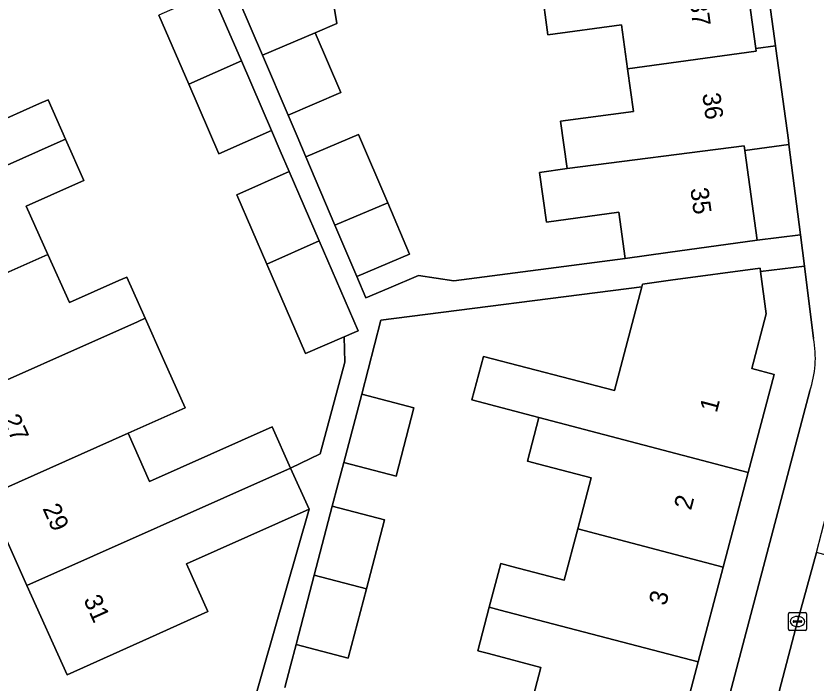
# Model space of a CAD drawing. Extents: x 163147 to 163550, y 380933 to 381639.
# Drawn here: x 163305.41 to 163349.73, y 381146.66 to 381183.65 of the extents above; entities that cross this region are included whole.
import ezdxf

# ---------------------------------------------------------------- set-up
doc = ezdxf.new("R2010")
doc.units = 0
for name, color, linetype in [('IMGEO_Erf', 7, 'Continuous'), ('IMGEO_Kolk', 7, 'Continuous'), ('IMGEO_Pand', 7, 'Continuous'), ('IMGEO_Pand_nummerreeks', 7, 'Continuous'), ('IMGEO_Rijbaan_lokaal_open', 7, 'Continuous'), ('IMGEO_Voetpad_open', 7, 'Continuous')]:
    doc.layers.add(name, color=color, linetype=linetype)

msp = doc.modelspace()

# ---------------------------------------------------------------- linework, layer by layer
at = {"layer": 'IMGEO_Erf'}
for points in [[(163346.127, 381191.825), (163345.039, 381191.675), (163345.711, 381186.784), (163346.388, 381181.854), (163347.476, 381182.004)], [(163348.228, 381176.531), (163345.784, 381176.195), (163346.465, 381171.235), (163348.863, 381171.54)]]:
    msp.add_lwpolyline(points, close=True, dxfattribs=at)
for points in [[(163322.634, 381186.622), (163323.179, 381183.235), (163321.987, 381182.727), (163323.4, 381179.41), (163320.478, 381178.166), (163320.979, 381176.991), (163321.463, 381175.854), (163324.384, 381177.098), (163326.001, 381173.304), (163327.21, 381170.465), (163324.289, 381169.221), (163324.79, 381168.045), (163326.066, 381168.588), (163327.711, 381169.289), (163329.659, 381168.981), (163339.151, 381170.231), (163338.8, 381172.786), (163334.788, 381172.235), (163334.409, 381174.99), (163335.937, 381175.2), (163335.579, 381177.82), (163339.611, 381178.372), (163339.288, 381180.725), (163338.953, 381183.168), (163334.875, 381182.608), (163334.513, 381185.247)], [(163303.971, 381177.58), (163306.712, 381178.8), (163307.181, 381179.008), (163308.15, 381176.83), (163309.167, 381174.546), (163308.711, 381174.343), (163305.97, 381173.124), (163307.17, 381170.451), (163308.368, 381167.78), (163311.109, 381168.999), (163311.548, 381169.194), (163312.564, 381166.91), (163313.58, 381164.626), (163314.77, 381161.953), (163311.613, 381160.548), (163312.812, 381157.875), (163319.597, 381160.894), (163320.621, 381158.613), (163322.266, 381159.409), (163323.626, 381164.485), (163323.596, 381165.887), (163321.443, 381164.955), (163319.299, 381169.906), (163317.634, 381173.75), (163320.543, 381175.044), (163320.051, 381176.181), (163319.562, 381177.31), (163316.653, 381176.016), (163314.984, 381179.869), (163313.326, 381183.697)], [(163349.596, 381165.787), (163349.084, 381169.804), (163346.653, 381169.495), (163346.974, 381167.164), (163346.173, 381164.127), (163347.401, 381163.803), (163345.971, 381158.376), (163344.588, 381153.128), (163343.205, 381147.878), (163341.822, 381142.63)], [(163333.739, 381144.749), (163334.49, 381147.578), (163331.588, 381148.339), (163330.992, 381148.495), (163331.626, 381150.913), (163332.26, 381153.331), (163332.871, 381153.171), (163335.773, 381152.411), (163336.524, 381155.242), (163337.275, 381158.071), (163334.373, 381158.831), (163333.745, 381158.996), (163334.38, 381161.414), (163330.669, 381162.387), (163331.31, 381164.803), (163338.557, 381162.903), (163340.084, 381168.658), (163325.613, 381166.816), (163324.563, 381162.709), (163327.456, 381161.951), (163326.46, 381158.158), (163323.567, 381158.917), (163323.246, 381157.696), (163322.932, 381156.501), (163325.825, 381155.742), (163324.821, 381151.924), (163323.831, 381148.154), (163323.815, 381148.093), (163320.923, 381148.853), (163320.612, 381147.671), (163320.294, 381146.461)], [(163334.439, 381106.274), (163349.385, 381162.891)], [(163304.985, 381145.89), (163307.687, 381144.941), (163309.044, 381145.786), (163318.448, 381145.215), (163321.644, 381156.332), (163314.859, 381153.313), (163316.043, 381150.675), (163312.795, 381149.218), (163308.233, 381147.171), (163306.015, 381152.115), (163303.793, 381157.068)]]:
    msp.add_lwpolyline(points, dxfattribs=at)
msp.add_arc((163343.933, 381164.744), 5.758, 341.2296, 10.4361, dxfattribs=at)
at = {"layer": 'IMGEO_Kolk'}
for p, q in [((163348.2, 381149.692), (163348.2, 381150.544)), ((163348.275, 381150.618), (163349.127, 381150.618)), ((163349.201, 381150.544), (163349.201, 381149.692)), ((163348.459, 381150.112), (163348.459, 381150.124)), ((163348.897, 381150.075), (163348.499, 381150.075)), ((163348.502, 381150.161), (163348.9, 381150.161)), ((163348.688, 381150.398), (163348.713, 381150.398)), ((163348.943, 381150.124), (163348.943, 381150.112)), ((163349.127, 381149.618), (163348.275, 381149.618)), ((163348.711, 381149.838), (163348.686, 381149.838))]:
    msp.add_line(p, q, dxfattribs=at)
for points in [[(163348.2, 381149.692), (163348.2, 381150.544)], [(163348.275, 381150.618), (163349.127, 381150.618)], [(163349.201, 381150.544), (163349.201, 381149.692)], [(163349.127, 381149.618), (163348.275, 381149.618)]]:
    msp.add_lwpolyline(points, dxfattribs=at)
for centre, radius, start, end in [((163348.277, 381150.542), 0.0765, 91.552, 178.448), ((163348.277, 381150.542), 0.0765, 91.552, 178.448), ((163349.125, 381150.542), 0.0765, 1.552, 88.448), ((163349.125, 381150.542), 0.0765, 1.552, 88.448), ((163348.499, 381150.121), 0.0403, 85.8775, 175.7526), ((163348.496, 381150.111), 0.0366, 178.938, 274.7102), ((163348.9, 381150.118), 0.043, 264.8664, 352.4533), ((163348.904, 381150.123), 0.0386, 1.7309, 96.639), ((163348.277, 381149.694), 0.0765, 181.552, 268.448), ((163348.277, 381149.694), 0.0765, 181.552, 268.448), ((163349.125, 381149.694), 0.0765, 271.552, 358.448), ((163349.125, 381149.694), 0.0765, 271.552, 358.448)]:
    msp.add_arc(centre, radius, start, end, dxfattribs=at)
for centre, major_axis, ratio, start_param, end_param in [((163348.687, 381150.118), (-0.387, 0.002), 0.722429, 4.712389, 7.853982), ((163348.712, 381150.118), (-0.39, 0.002), 0.717154, 1.570796, 4.712389)]:
    msp.add_ellipse(centre, major_axis=major_axis, ratio=ratio, start_param=start_param, end_param=end_param, dxfattribs=at)
at = {"layer": 'IMGEO_Pand'}
for points in [[(163345.711, 381186.784), (163334.513, 381185.247), (163334.875, 381182.608), (163338.953, 381183.168), (163339.288, 381180.725), (163346.409, 381181.702), (163346.388, 381181.854)], [(163317.761, 381184.545), (163319.065, 381181.482), (163321.987, 381182.727), (163323.179, 381183.235), (163322.634, 381186.622)], [(163316.235, 381184.991), (163313.326, 381183.697), (163314.984, 381179.869), (163317.893, 381181.163)], [(163321.987, 381182.727), (163319.065, 381181.482), (163320.478, 381178.166), (163323.4, 381179.41)], [(163347.497, 381181.851), (163347.476, 381182.004), (163346.388, 381181.854), (163346.409, 381181.702), (163339.288, 381180.725), (163339.611, 381178.372), (163335.579, 381177.82), (163335.937, 381175.2), (163345.748, 381176.457), (163345.784, 381176.195), (163348.228, 381176.531), (163348.195, 381176.771)], [(163317.893, 381181.163), (163314.984, 381179.869), (163316.653, 381176.016), (163319.562, 381177.31)], [(163308.15, 381176.83), (163307.181, 381179.008), (163306.712, 381178.8), (163303.971, 381177.58), (163302.725, 381180.356), (163294.905, 381176.877), (163297.126, 381171.926), (163307.688, 381176.624)], [(163321.463, 381175.854), (163323.08, 381172.059), (163326.001, 381173.304), (163324.384, 381177.098)], [(163305.97, 381173.124), (163308.711, 381174.343), (163309.167, 381174.546), (163308.15, 381176.83), (163307.688, 381176.624), (163297.126, 381171.926), (163299.349, 381166.972), (163307.17, 381170.451)], [(163345.784, 381176.195), (163345.748, 381176.457), (163335.937, 381175.2), (163334.409, 381174.99), (163334.788, 381172.235), (163338.8, 381172.786), (163339.151, 381170.231), (163341.512, 381170.555), (163346.465, 381171.235)], [(163320.543, 381175.044), (163317.634, 381173.75), (163319.299, 381169.906), (163322.208, 381171.2)], [(163326.001, 381173.304), (163323.08, 381172.059), (163324.289, 381169.221), (163327.21, 381170.465)], [(163322.208, 381171.2), (163319.299, 381169.906), (163321.443, 381164.955), (163323.596, 381165.887), (163324.148, 381166.126), (163324.364, 381166.222)], [(163311.548, 381169.194), (163311.109, 381168.999), (163308.368, 381167.78), (163307.17, 381170.451), (163299.349, 381166.972), (163301.571, 381162.02), (163312.133, 381166.718), (163312.564, 381166.91)], [(163346.974, 381167.164), (163346.653, 381169.495), (163346.626, 381169.693), (163341.673, 381169.013), (163340.122, 381168.8), (163340.084, 381168.658), (163338.557, 381162.903), (163331.31, 381164.803), (163330.669, 381162.387), (163334.38, 381161.414), (163345.971, 381158.376), (163347.401, 381163.803), (163346.173, 381164.127)], [(163313.58, 381164.626), (163312.564, 381166.91), (163312.133, 381166.718), (163301.571, 381162.02), (163303.793, 381157.068), (163311.613, 381160.548), (163314.77, 381161.953)], [(163324.563, 381162.709), (163323.567, 381158.917), (163326.46, 381158.158), (163327.456, 381161.951)], [(163345.971, 381158.376), (163334.38, 381161.414), (163333.745, 381158.996), (163334.373, 381158.831), (163337.275, 381158.071), (163336.524, 381155.242), (163344.588, 381153.128)], [(163306.015, 381152.115), (163320.621, 381158.613), (163319.597, 381160.894), (163312.812, 381157.875), (163311.613, 381160.548), (163303.793, 381157.068)], [(163306.015, 381152.115), (163308.233, 381147.171), (163312.795, 381149.218), (163316.043, 381150.675), (163314.859, 381153.313), (163321.644, 381156.332), (163320.621, 381158.613)], [(163322.932, 381156.501), (163321.929, 381152.683), (163324.821, 381151.924), (163325.825, 381155.742)], [(163344.588, 381153.128), (163336.524, 381155.242), (163335.773, 381152.411), (163332.871, 381153.171), (163332.26, 381153.331), (163331.626, 381150.913), (163332.229, 381150.755), (163343.205, 381147.878)], [(163324.821, 381151.924), (163321.929, 381152.683), (163320.939, 381148.914), (163320.923, 381148.853), (163323.815, 381148.093), (163323.831, 381148.154)], [(163343.205, 381147.878), (163332.229, 381150.755), (163331.626, 381150.913), (163330.992, 381148.495), (163331.588, 381148.339), (163334.49, 381147.578), (163333.739, 381144.749), (163341.822, 381142.63)]]:
    msp.add_lwpolyline(points, close=True, dxfattribs=at)
at = {"layer": 'IMGEO_Rijbaan_lokaal_open'}
msp.add_lwpolyline([(163354.555, 381152.632), (163349.764, 381153.947), (163348.698, 381150.118), (163343.238, 381129.253), (163342.145, 381125.04), (163346.987, 381123.777), (163348.081, 381128.004), (163349.629, 381133.907), (163350.968, 381139.012), (163351.744, 381141.971), (163353.081, 381147.071), (163353.695, 381149.411)], close=True, dxfattribs=at)
at = {"layer": 'IMGEO_Voetpad_open'}
for points in [[(163333.923, 381291.813), (163330.728, 381291.79), (163331.089, 381289.4), (163333.107, 381289.679), (163334.924, 381276.051), (163335.797, 381269.508), (163336.166, 381266.742), (163336.175, 381266.672), (163336.432, 381264.739), (163338.386, 381250), (163344.525, 381203.718), (163344.714, 381202.289), (163345.388, 381197.208), (163345.403, 381197.095), (163346.101, 381192.014), (163346.127, 381191.825), (163347.476, 381182.004), (163347.497, 381181.851), (163348.195, 381176.771), (163348.228, 381176.531), (163348.863, 381171.54), (163349.084, 381169.804), (163349.596, 381165.787)], [(163316.235, 381184.991), (163317.893, 381181.163), (163319.562, 381177.31), (163320.051, 381176.181), (163320.543, 381175.044), (163322.208, 381171.2), (163324.364, 381166.222), (163324.148, 381166.126), (163323.596, 381165.887), (163323.626, 381164.485), (163322.266, 381159.409), (163320.621, 381158.613), (163321.644, 381156.332), (163318.448, 381145.215), (163316.034, 381135.723), (163315.715, 381134.476), (163313.079, 381124.337), (163310.086, 381120.226), (163298.375, 381132.601)], [(163320.294, 381146.461), (163320.612, 381147.671), (163320.923, 381148.853), (163320.939, 381148.914), (163321.929, 381152.683), (163322.932, 381156.501), (163323.246, 381157.696), (163323.567, 381158.917), (163324.563, 381162.709), (163325.613, 381166.816), (163340.084, 381168.658), (163340.122, 381168.8), (163341.673, 381169.013), (163346.626, 381169.693), (163346.653, 381169.495), (163349.084, 381169.804), (163348.863, 381171.54), (163346.465, 381171.235), (163341.512, 381170.555), (163339.151, 381170.231), (163329.659, 381168.981), (163327.711, 381169.289), (163326.066, 381168.588), (163324.79, 381168.045), (163324.289, 381169.221), (163323.08, 381172.059), (163321.463, 381175.854), (163320.979, 381176.991), (163320.478, 381178.166), (163319.065, 381181.482), (163317.761, 381184.545)], [(163349.385, 381162.891), (163334.439, 381106.274), (163328.748, 381100.437), (163328.567, 381100.252), (163327.566, 381099.224), (163327.46, 381099.116), (163325.705, 381097.476), (163310.741, 381082.456), (163311.048, 381082.128), (163310.809, 381081.904), (163310.55, 381082.181), (163308.363, 381080.136), (163308.588, 381079.896), (163307.821, 381079.179), (163307.591, 381079.425), (163305.465, 381077.436), (163305.767, 381077.113), (163305.592, 381076.949), (163307.948, 381074.335), (163325.917, 381092.562), (163328.54, 381095.222), (163335.379, 381102.16)], [(163336.678, 381104.171), (163337.355, 381106.775), (163338.283, 381110.344), (163340.318, 381118.106), (163341.295, 381121.826), (163342.145, 381125.04), (163343.238, 381129.253), (163348.698, 381150.118), (163349.764, 381153.947), (163350.589, 381157.148), (163351.104, 381159.046), (163351.813, 381161.75)]]:
    msp.add_lwpolyline(points, dxfattribs=at)
msp.add_arc((163343.933, 381164.744), 5.758, 341.2296, 10.4361, dxfattribs=at)

# ---------------------------------------------------------------- texts
at = {"layer": 'IMGEO_Pand_nummerreeks'}
for s, rotation, p in [('37', 277.8207, (163342.713, 381184.509)), ('36', 277.8207, (163343.423, 381179.339)), ('35', 277.8149, (163342.762, 381174.089)), ('1', 75.2408, (163344.226, 381161.643)), ('27', 294.1614, (163304.641, 381161.333)), ('2', 75.2408, (163342.802, 381156.24)), ('29', 294.1641, (163306.862, 381156.383)), ('3', 75.2408, (163341.408, 381150.951)), ('31', 294.1641, (163309.129, 381151.329))]:
    msp.add_text(s, height=1, rotation=rotation, dxfattribs=at).set_placement(p)

doc.saveas('drawing.dxf')
